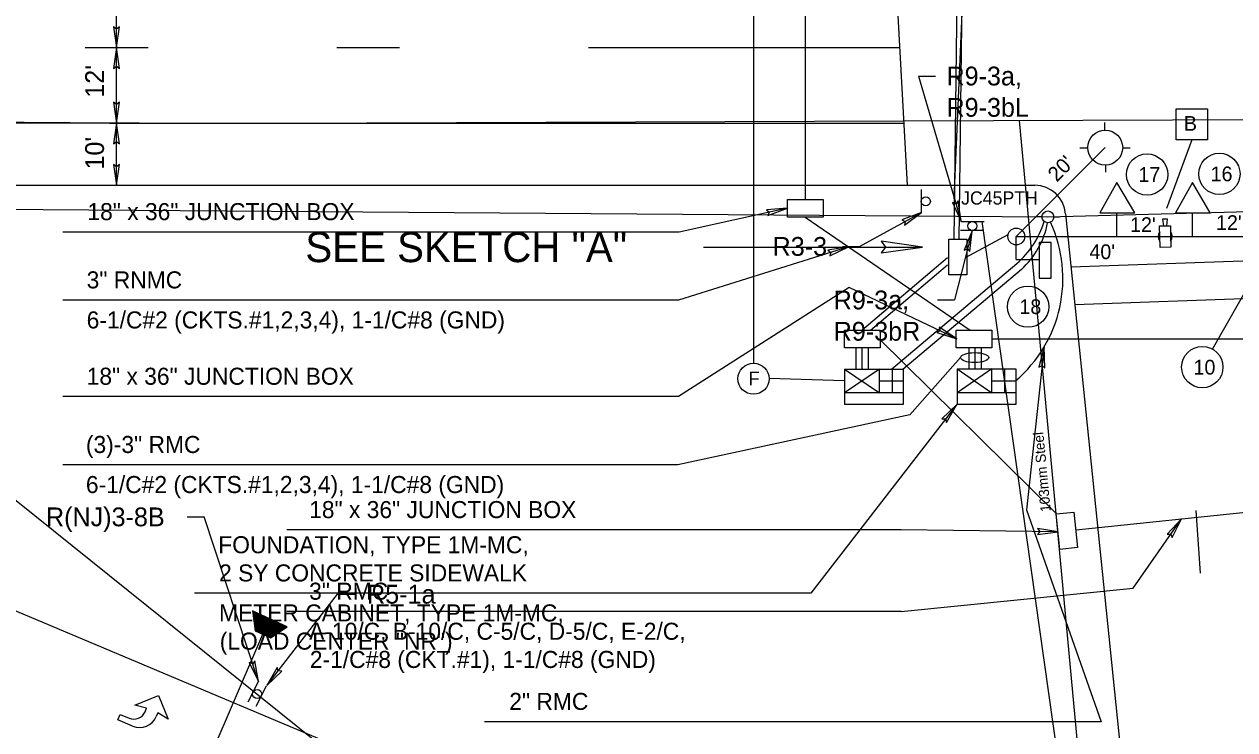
# Model space of a CAD drawing. Extents: x 488740 to 507913, y 466518 to 497949.
# Drawn here: x 503306.1 to 503498.8, y 495932.7 to 496045.1 of the extents above; entities that cross this region are included whole.
import ezdxf

# ---------------------------------------------------------------- set-up
doc = ezdxf.new("R2010")
doc.units = 0
for name, color, linetype in [('1', 7, 'Continuous'), ('11', 7, 'Continuous'), ('23', 7, 'Continuous'), ('31', 7, 'Continuous'), ('36', 7, 'Continuous'), ('38', 7, 'Continuous'), ('41', 7, 'Continuous'), ('5', 7, 'Continuous'), ('7', 7, 'Continuous'), ('9', 7, 'Continuous')]:
    doc.layers.add(name, color=color, linetype=linetype)

msp = doc.modelspace()

# ---------------------------------------------------------------- linework, layer by layer
at = {"layer": '1'}
for p, q in [((503325.93, 496019.46), (503467, 496019.46)), ((503468.17, 496014.44), (503467.3, 496014.44)), ((503470.04, 496014.44), (503470.95, 496014.44)), ((503471.88, 496014.92), (503482.9, 495907.73)), ((503268.83, 495966.81), (503425.13, 495900.97))]:
    msp.add_line(p, q, dxfattribs=at)
msp.add_circle((503469.08, 496014.43), 0.939, dxfattribs=at)
for centre, radius, start, end in [((503325.29, 501769.95), 5750.49, 269.44715, 270.006342), ((503467, 496014.56), 4.9, 4.1335, 90)]:
    msp.add_arc(centre, radius, start, end, dxfattribs=at)
at = {"layer": '11'}
for p, q in [((503427.6, 496015.8), (503410.38, 496012.02)), ((503410.38, 496012.02), (503312.2, 496012.02)), ((503437.34, 496009.65), (503410.26, 496001.15)), ((503410.26, 496001.15), (503312.2, 496001.15)), ((503468.48, 495993.71), (503465.65, 495967.79)), ((503410.26, 495985.8), (503312.2, 495985.8)), ((503454.56, 495984.57), (503431.34, 495954.47)), ((503410.15, 495974.93), (503312.2, 495974.93)), ((503465.65, 495967.79), (503477.57, 495934.01)), ((503431.34, 495954.47), (503333.16, 495954.47)), ((503477.57, 495934.01), (503379.38, 495934.01))]:
    msp.add_line(p, q, dxfattribs=at)
for points in [[(503427.6, 496015.8), (503424.27, 496015.55), (503424.72, 496015.17), (503424.47, 496014.63)], [(503437.34, 496009.65), (503434.04, 496009.11), (503434.52, 496008.76), (503434.33, 496008.21)], [(503454.56, 495994.99), (503451.78, 495996.84), (503451.9, 495996.26), (503451.37, 495995.99)], [(503468.48, 495993.71), (503467.65, 495990.48), (503468.16, 495990.78), (503468.59, 495990.38)], [(503454.56, 495984.57), (503452.17, 495982.24), (503452.76, 495982.24), (503452.91, 495981.67)]]:
    msp.add_lwpolyline(points, close=True, dxfattribs=at)
for points in [[(503454.56, 495994.99), (503437.45, 496003.17), (503410.26, 495985.8)], [(503455.19, 495992.02), (503447.1, 495982.9), (503410.15, 495974.93)]]:
    msp.add_lwpolyline(points, dxfattribs=at)
msp.add_ellipse((503457.42, 495992.02), major_axis=(-2.23, 0), ratio=0.356808, dxfattribs=at)
at = {"layer": '23'}
for p, q in [((503462.78, 496220.08), (503454.1, 496017.3)), ((503346.41, 496029.35), (503748.62, 496030.81)), ((503478.95, 495875.52), (503464.57, 496029.78)), ((503469.08, 496014.43), (503748.62, 496022.1)), ((503234.58, 496016.17), (503469.08, 496014.43)), ((503481.44, 495851.92), (503458.62, 496013.71)), ((503280.37, 495988.85), (503393.56, 495897.96)), ((503342.44, 495951.59), (503347.9, 495949.11)), ((503342.45, 495951.51), (503347.83, 495949.06)), ((503342.46, 495951.43), (503347.76, 495949.02)), ((503342.47, 495951.35), (503347.7, 495948.98)), ((503342.48, 495951.27), (503347.63, 495948.93)), ((503342.49, 495951.19), (503347.56, 495948.89)), ((503342.5, 495951.11), (503347.5, 495948.84)), ((503342.51, 495951.04), (503347.43, 495948.8)), ((503342.52, 495950.96), (503347.36, 495948.76)), ((503342.53, 495950.88), (503347.3, 495948.71)), ((503342.55, 495950.8), (503347.23, 495948.67)), ((503342.56, 495950.72), (503347.17, 495948.62)), ((503342.57, 495950.64), (503347.1, 495948.58)), ((503342.58, 495950.56), (503347.03, 495948.53)), ((503342.59, 495950.48), (503346.97, 495948.49)), ((503342.6, 495950.4), (503346.9, 495948.45)), ((503342.61, 495950.33), (503346.83, 495948.4)), ((503342.62, 495950.25), (503346.77, 495948.36)), ((503342.63, 495950.17), (503346.7, 495948.32)), ((503342.64, 495950.09), (503346.63, 495948.27)), ((503342.65, 495950.01), (503346.57, 495948.23)), ((503342.66, 495949.93), (503346.5, 495948.18)), ((503342.67, 495949.85), (503346.44, 495948.14)), ((503342.68, 495949.77), (503346.37, 495948.1)), ((503342.69, 495949.69), (503346.3, 495948.05)), ((503342.7, 495949.61), (503346.24, 495948.01)), ((503342.71, 495949.54), (503346.17, 495947.96)), ((503342.72, 495949.46), (503346.1, 495947.92)), ((503342.73, 495949.38), (503346.04, 495947.88)), ((503342.74, 495949.3), (503345.97, 495947.83)), ((503342.75, 495949.22), (503345.9, 495947.79)), ((503342.77, 495949.14), (503345.84, 495947.74)), ((503342.78, 495949.06), (503345.77, 495947.7)), ((503342.79, 495948.98), (503345.71, 495947.66)), ((503342.8, 495948.9), (503345.64, 495947.61)), ((503342.81, 495948.83), (503345.57, 495947.57)), ((503342.82, 495948.75), (503345.51, 495947.52)), ((503328.98, 495912.96), (503344.08, 495947.95)), ((503342.83, 495948.67), (503345.44, 495947.48)), ((503342.84, 495948.59), (503345.37, 495947.44)), ((503344.08, 495947.95), (503344.08, 495947.95))]:
    msp.add_line(p, q, dxfattribs=at)
msp.add_lwpolyline([(503342.85, 495948.51), (503345.31, 495947.39), (503347.96, 495949.15), (503342.43, 495951.67)], close=True, dxfattribs=at)
msp.add_arc((503345.84, 500783.2), 4753.85, 267.1758, 270.00684, dxfattribs=at)
at = {"layer": '31'}
for p, q in [((503480.07, 496011.3), (503480.07, 496015.08)), ((503492.09, 496011.3), (503492.09, 496015.08)), ((503464.05, 496011.3), (503504.11, 496011.3)), ((503464.05, 496007.64), (503464.05, 496011.3)), ((503464.05, 496007.64), (503467.71, 496007.64)), ((503495.29, 495993.35), (503501.81, 496004.81))]:
    msp.add_line(p, q, dxfattribs=at)
for points in [[(503480.07, 496019.92), (503477.36, 496015.08), (503480.07, 496015.08), (503482.91, 496015.08)], [(503492.09, 496019.92), (503489.38, 496015.08), (503492.09, 496015.08), (503494.93, 496015.08)], [(503469.6, 496004.68), (503469.6, 496010.35), (503467.71, 496010.35), (503467.71, 496004.68)]]:
    msp.add_lwpolyline(points, close=True, dxfattribs=at)
for centre, radius in [((503484.88, 496021.18), 3.29), ((503496.39, 496021.28), 3.29), ((503464.05, 496011.3), 1.34), ((503465.93, 496000.13), 3.29), ((503493.67, 495990.5), 3.29)]:
    msp.add_circle(centre, radius, dxfattribs=at)
at = {"layer": '36'}
for p, q in [((503446.71, 496019.46), (503443.98, 496069.39)), ((503315.77, 496041.39), (503325.78, 496041.39)), ((503355.83, 496041.4), (503365.85, 496041.4)), ((503395.9, 496041.4), (503445.51, 496041.4)), ((503326.93, 496029.38), (503446.17, 496029.38)), ((503581.59, 496010.27), (503472.76, 496006.44)), ((503581.68, 496004.26), (503473.37, 496000.44)), ((503493.4, 495957.69), (503492.67, 495967.68)), ((503323.67, 495936.64), (503327.44, 495938.18)), ((503327.44, 495938.18), (503328.98, 495934.4)), ((503320.95, 495934.31), (503321.32, 495935.19)), ((503321.32, 495935.19), (503322.8, 495934.57)), ((503325.56, 495936.19), (503323.67, 495936.64)), ((503325.31, 495935.6), (503325.56, 495936.19)), ((503327.34, 495935.44), (503327.09, 495934.85)), ((503328.98, 495934.4), (503327.34, 495935.44)), ((503323.31, 495933.31), (503320.95, 495934.31))]:
    msp.add_line(p, q, dxfattribs=at)
for centre, radius, start, end in [((503463.07, 496039.06), 48.52, 0.3384, 83.5869), ((503325.29, 501769.95), 5740.57, 267.688922, 270.016331), ((503323.54, 495936.34), 1.92, 247.157, 337.157), ((503324.43, 495935.97), 2.88, 247.157, 337.157)]:
    msp.add_arc(centre, radius, start, end, dxfattribs=at)
at = {"layer": '38'}
for p, q in [((503320.78, 496041.39), (503320.78, 496053.41)), ((503320.78, 496029.38), (503320.78, 496041.39)), ((503320.78, 496019.47), (503320.78, 496029.38))]:
    msp.add_line(p, q, dxfattribs=at)
for points in [[(503320.78, 496041.39), (503321.25, 496044.7), (503320.78, 496044.34), (503320.3, 496044.7)], [(503320.78, 496041.39), (503320.3, 496038.08), (503320.78, 496038.44), (503321.25, 496038.08)], [(503320.78, 496029.38), (503321.25, 496032.69), (503320.78, 496032.34), (503320.3, 496032.69)], [(503320.78, 496029.38), (503320.3, 496026.08), (503320.78, 496026.43), (503321.25, 496026.08)], [(503320.78, 496019.47), (503321.25, 496022.77), (503320.78, 496022.42), (503320.3, 496022.77)]]:
    msp.add_lwpolyline(points, close=True, dxfattribs=at)
at = {"layer": '41'}
for p, q in [((503448.45, 496036.87), (503455.29, 496013.7)), ((503448.45, 496036.87), (503451.16, 496036.87)), ((503448.93, 496015.12), (503448.93, 496018.79)), ((503439.07, 496009.73), (503448.93, 496015.12)), ((503455.29, 496013.7), (503458.95, 496013.7)), ((503457, 496012.22), (503454.21, 496001.2)), ((503458.83, 496012.28), (503455.17, 496012.28)), ((503436.36, 496009.73), (503439.07, 496009.73)), ((503451.5, 496001.2), (503454.21, 496001.2)), ((503331.99, 495966.64), (503334.7, 495966.64)), ((503343.38, 495940.44), (503334.7, 495966.64)), ((503344.71, 495939.77), (503355.98, 495954.33)), ((503355.98, 495954.33), (503358.69, 495954.33)), ((503341.72, 495937.18), (503343.38, 495940.44)), ((503344.59, 495939.69), (503342.93, 495936.43))]:
    msp.add_line(p, q, dxfattribs=at)
for points in [[(503455.29, 496013.7), (503454.8, 496017.01), (503454.45, 496016.53), (503453.9, 496016.74)], [(503448.93, 496015.12), (503445.8, 496013.95), (503446.34, 496013.71), (503446.26, 496013.12)], [(503457, 496012.22), (503455.73, 496009.13), (503456.28, 496009.36), (503456.65, 496008.9)], [(503343.38, 495940.44), (503342.79, 495943.73), (503342.46, 495943.24), (503341.9, 495943.43)], [(503344.71, 495939.77), (503347.1, 495942.09), (503346.51, 495942.1), (503346.36, 495942.67)]]:
    msp.add_lwpolyline(points, close=True, dxfattribs=at)
for centre in [(503449.64, 496016.9), (503457.06, 496012.99), (503457.06, 496012.99), (503343.16, 495938.44), (503343.16, 495938.44)]:
    msp.add_circle(centre, 0.721, dxfattribs=at)
at = {"layer": '5'}
for p, q in [((503454.17, 496010.78), (503455.93, 496157.27)), ((503454.95, 496010.78), (503456.7, 496157)), ((503422.21, 496136.17), (503422.21, 495991.12)), ((503430.39, 496136.05), (503430.43, 496017.22)), ((503489.52, 496026.7), (503489.52, 496031.66)), ((503489.52, 496031.66), (503494.48, 496031.66)), ((503494.48, 496031.66), (503494.48, 496026.7)), ((503492, 496026.7), (503487.99, 496015.75)), ((503494.48, 496026.7), (503489.52, 496026.7)), ((503430.43, 496014.38), (503456.68, 495996.41)), ((503455.96, 496007.95), (503462.74, 496011.61)), ((503486.93, 496010.56), (503486.9, 496012.06)), ((503486.93, 496010.56), (503486.9, 496012.06)), ((503488.6, 496012.09), (503488.62, 496010.59)), ((503488.6, 496012.09), (503488.62, 496010.59)), ((503439.46, 495996.39), (503453.11, 496007.95)), ((503440.85, 495996.39), (503453.11, 496006.77)), ((503444.16, 495990.17), (503464.11, 496006.98)), ((503446, 495990.17), (503464.88, 496006.08)), ((503442.29, 495994.96), (503470.45, 495967.11)), ((503460.23, 495995), (503577.07, 495995)), ((503438.49, 495993.54), (503438.49, 495990.17)), ((503439.46, 495993.54), (503439.46, 495990.17)), ((503440.45, 495993.54), (503440.45, 495990.17)), ((503456.47, 495993.57), (503456.47, 495990.2)), ((503457.43, 495993.57), (503457.43, 495990.2)), ((503458.43, 495993.57), (503458.43, 495990.2)), ((503436.7, 495990.19), (503442.25, 495986.41)), ((503442.25, 495990.19), (503436.7, 495986.41)), ((503436.7, 495990.19), (503446.03, 495990.19)), ((503436.7, 495990.19), (503436.7, 495986.41)), ((503442.25, 495986.41), (503442.25, 495990.19)), ((503444.26, 495990.19), (503444.26, 495986.41)), ((503446.03, 495990.19), (503446.03, 495986.41)), ((503454.63, 495990.21), (503460.18, 495986.43)), ((503460.18, 495990.21), (503454.63, 495986.43)), ((503454.63, 495990.21), (503463.96, 495990.21)), ((503454.63, 495990.21), (503454.63, 495986.43)), ((503460.18, 495986.43), (503460.18, 495990.21)), ((503462.19, 495990.21), (503462.19, 495986.43)), ((503463.96, 495990.21), (503463.96, 495986.43)), ((503436.63, 495988.3), (503424.7, 495988.67)), ((503442.25, 495988.3), (503446.03, 495988.3)), ((503460.18, 495988.32), (503463.96, 495988.32)), ((503436.7, 495986.41), (503436.7, 495984.53)), ((503446.03, 495986.41), (503436.7, 495986.41)), ((503446.03, 495986.41), (503446.03, 495984.53)), ((503454.63, 495986.43), (503454.63, 495984.56)), ((503463.96, 495986.43), (503454.63, 495986.43)), ((503463.96, 495986.43), (503463.96, 495984.56)), ((503446.03, 495984.53), (503436.7, 495984.53)), ((503463.96, 495984.56), (503454.63, 495984.56)), ((503473.57, 495964.59), (503570.19, 495974.61))]:
    msp.add_line(p, q, dxfattribs=at)
for points in [[(503433.27, 496014.39), (503427.6, 496014.39), (503427.6, 496017.22), (503433.27, 496017.22), (503433.27, 496014.39)], [(503433.27, 496014.39), (503427.6, 496014.39), (503427.6, 496017.22), (503433.27, 496017.22), (503433.27, 496014.39)], [(503456.16, 496010.88), (503456.16, 496005.21), (503453.32, 496005.21), (503453.32, 496010.88), (503456.16, 496010.88)], [(503442.35, 495993.55), (503436.68, 495993.55), (503436.68, 495996.38), (503442.35, 495996.38), (503442.35, 495993.55)], [(503460.17, 495993.55), (503454.5, 495993.55), (503454.5, 495996.38), (503460.17, 495996.38), (503460.17, 495993.55)], [(503473.21, 495967.4), (503473.79, 495961.76), (503470.97, 495961.47), (503470.39, 495967.11), (503473.21, 495967.4)]]:
    msp.add_lwpolyline(points, dxfattribs=at)
for points in [[(503488.59, 496013.01), (503488.65, 496009.61), (503486.94, 496009.58), (503486.88, 496012.98)], [(503488.59, 496013.01), (503488.65, 496009.61), (503486.94, 496009.58), (503486.88, 496012.98)], [(503488.02, 496013), (503488.15, 496014.07), (503487.32, 496014.05), (503487.49, 496012.99)], [(503488.02, 496013), (503488.15, 496014.07), (503487.32, 496014.05), (503487.49, 496012.99)]]:
    msp.add_lwpolyline(points, close=True, dxfattribs=at)
msp.add_circle((503422.21, 495988.65), 2.48, dxfattribs=at)
for centre, radius, start, end in [((503450.09, 496004.62), 21.38, 310.3663, 24.7939), ((503454.56, 496018.04), 14.61, 310.8103, 342.6393), ((503455.68, 496016.12), 13.62, 312.4616, 348.8434), ((503487.76, 496011.33), 1.13, 139.5759, 222.3955), ((503487.76, 496011.33), 1.13, 139.5759, 222.3955), ((503487.76, 496011.33), 1.13, 319.5761, 42.394), ((503487.76, 496011.33), 1.13, 319.5761, 42.394)]:
    msp.add_arc(centre, radius, start, end, dxfattribs=at)
at = {"layer": '7'}
for p, q in [((503478.17, 496028.24), (503478.17, 496029.45)), ((503464.05, 496011.3), (503478.21, 496025.46)), ((503474.16, 496025.44), (503475.43, 496025.44)), ((503478.21, 496025.46), (503478.21, 496025.46)), ((503480.99, 496025.44), (503482.18, 496025.44)), ((503478.3, 496021.54), (503478.3, 496022.71))]:
    msp.add_line(p, q, dxfattribs=at)
msp.add_circle((503478.21, 496025.46), 2.78, dxfattribs=at)
at = {"layer": '9'}
for p, q in [((503414.23, 496009.62), (503449.13, 496009.62)), ((503482.68, 495955.31), (503490.36, 495966.33)), ((503445.69, 495964.56), (503347.86, 495964.56)), ((503470.74, 495964.29), (503445.69, 495964.56)), ((503445.69, 495951.56), (503482.68, 495955.31)), ((503445.69, 495951.56), (503347.86, 495951.56))]:
    msp.add_line(p, q, dxfattribs=at)
for points in [[(503449.13, 496009.62), (503442.51, 496010.57), (503443.22, 496009.62), (503442.51, 496008.68)], [(503490.36, 495966.33), (503488.08, 495963.88), (503488.67, 495963.91), (503488.86, 495963.34)], [(503470.74, 495964.29), (503467.44, 495964.8), (503467.79, 495964.33), (503467.43, 495963.86)]]:
    msp.add_lwpolyline(points, close=True, dxfattribs=at)

# ---------------------------------------------------------------- texts
at = {"layer": '1'}
msp.add_text('JC45PTH', height=2.109, dxfattribs=at).set_placement((503455.26, 496016.39))
at = {"layer": '11'}
for s, p in [('18" x 36" JUNCTION BOX             ', (503316.13, 496013.91)), ('3" RNMC                            ', (503316.01, 496003.04)), ('6-1/C#2 (CKTS.#1,2,3,4), 1-1/C#8 (GND)         ', (503316.01, 495996.66)), ('18" x 36" JUNCTION BOX             ', (503316.01, 495987.69)), ('(3)-3" RMC                         ', (503315.89, 495976.82)), ('6-1/C#2 (CKTS.#1,2,3,4), 1-1/C#8 (GND)         ', (503315.89, 495970.44)), ('FOUNDATION, TYPE 1M-MC,            ', (503336.97, 495960.85)), ('2 SY CONCRETE SIDEWALK             ', (503337.09, 495956.36)), ('METER CABINET, TYPE 1M-MC,                     ', (503337.09, 495949.99)), ('(LOAD CENTER "NR")                             ', (503337.2, 495945.5)), ('2" RMC                             ', (503383.31, 495935.9))]:
    msp.add_text(s, height=2.7163, dxfattribs=at).set_placement(p)
at = {"layer": '23'}
msp.add_text('103mm Steel', height=1.6204, rotation=95.3255, dxfattribs=at).set_placement((503469.54, 495967.52))
at = {"layer": '31'}
for s, p in [('17', (503483.49, 496020.01)), ('16', (503494.99, 496020.11)), ("12'", (503482.17, 496012.02)), ("12'", (503495.85, 496012.35)), ("40'", (503475.69, 496007.71)), ('18', (503464.54, 495998.96)), ('10', (503492.27, 495989.32))]:
    msp.add_text(s, height=2.344, dxfattribs=at).set_placement(p)
at = {"layer": '38'}
for s, p in [("12'", (503318.77, 496033.41)), ("10'", (503318.77, 496021.97))]:
    msp.add_text(s, height=2.993, rotation=90, dxfattribs=at).set_placement(p)
at = {"layer": '41'}
for s, p in [('R9-3a,', (503452.93, 496035.37)), ('R9-3bL', (503452.93, 496030.38)), ('R3-3', (503425.24, 496008.23)), ('R9-3a,', (503434.97, 495999.7)), ('R9-3bR', (503434.97, 495994.71)), ('R(NJ)3-8B', (503309.53, 495965.15)), ('R5-1a', (503360.66, 495952.83))]:
    msp.add_text(s, height=2.993, dxfattribs=at).set_placement(p)
at = {"layer": '5'}
msp.add_text('B', height=2.34, dxfattribs=at).set_placement((503490.73, 496028.15))
msp.add_text('F', height=2.2, rotation=360, dxfattribs=at).set_placement((503421.39, 495987.59))
at = {"layer": '7'}
msp.add_text("20'", height=2.344, rotation=45.0002, dxfattribs=at).set_placement((503470.49, 496019.89))
at = {"layer": '9'}
for s, height, p in [('SEE SKETCH "A"', 4.7957, (503350.83, 496007.22)), ('18" x 36" JUNCTION BOX                  ', 2.7163, (503351.44, 495966.45)), ('3" RMC                                  ', 2.7163, (503351.44, 495953.45)), ('A-10/C, B-10/C, C-5/C, D-5/C, E-2/C,    ', 2.7163, (503351.44, 495947.07)), ('2-1/C#8 (CKT.#1), 1-1/C#8 (GND)         ', 2.7163, (503351.55, 495942.58))]:
    msp.add_text(s, height=height, dxfattribs=at).set_placement(p)

doc.saveas('drawing.dxf')
